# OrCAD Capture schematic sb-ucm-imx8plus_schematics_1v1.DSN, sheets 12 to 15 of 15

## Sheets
12 12. M.2 Key B, PCIe, USB3: size A3; title: SB-UCM-iMX8PLUS    12. PCIe
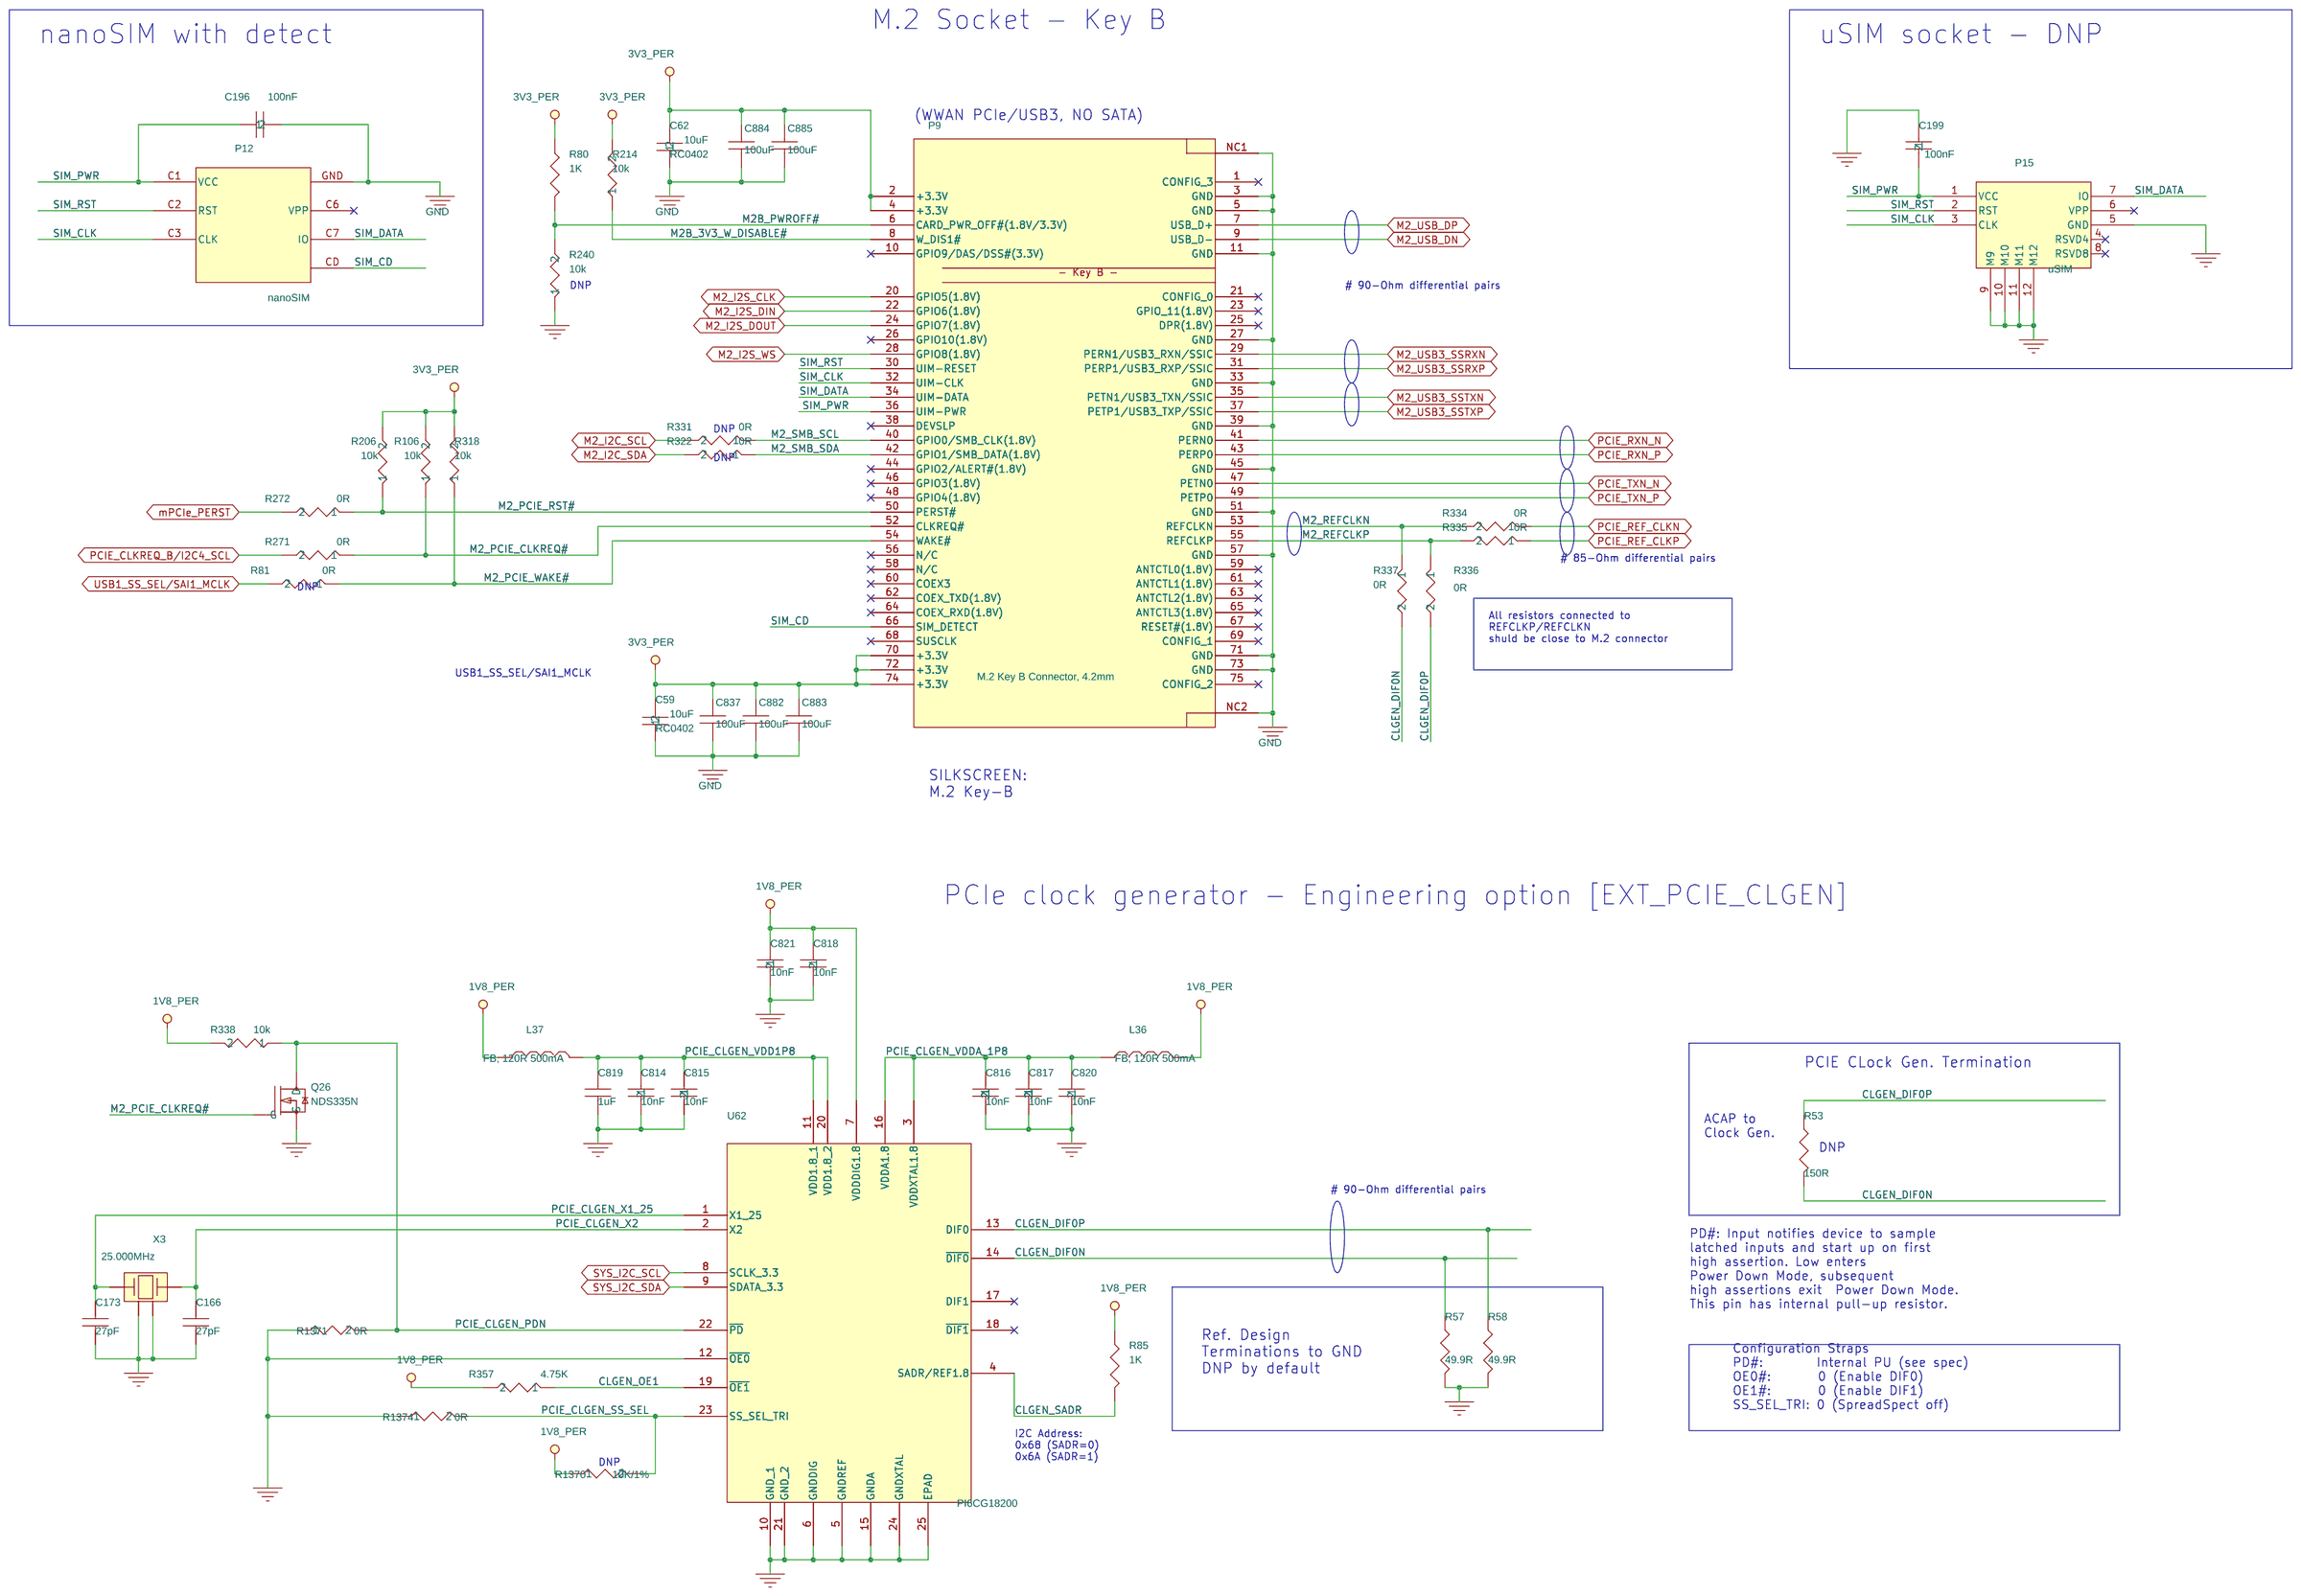
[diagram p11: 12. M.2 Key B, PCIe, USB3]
13 13. Power: size A3; title: SB-UCM-iMX8PLUS    13. POWER
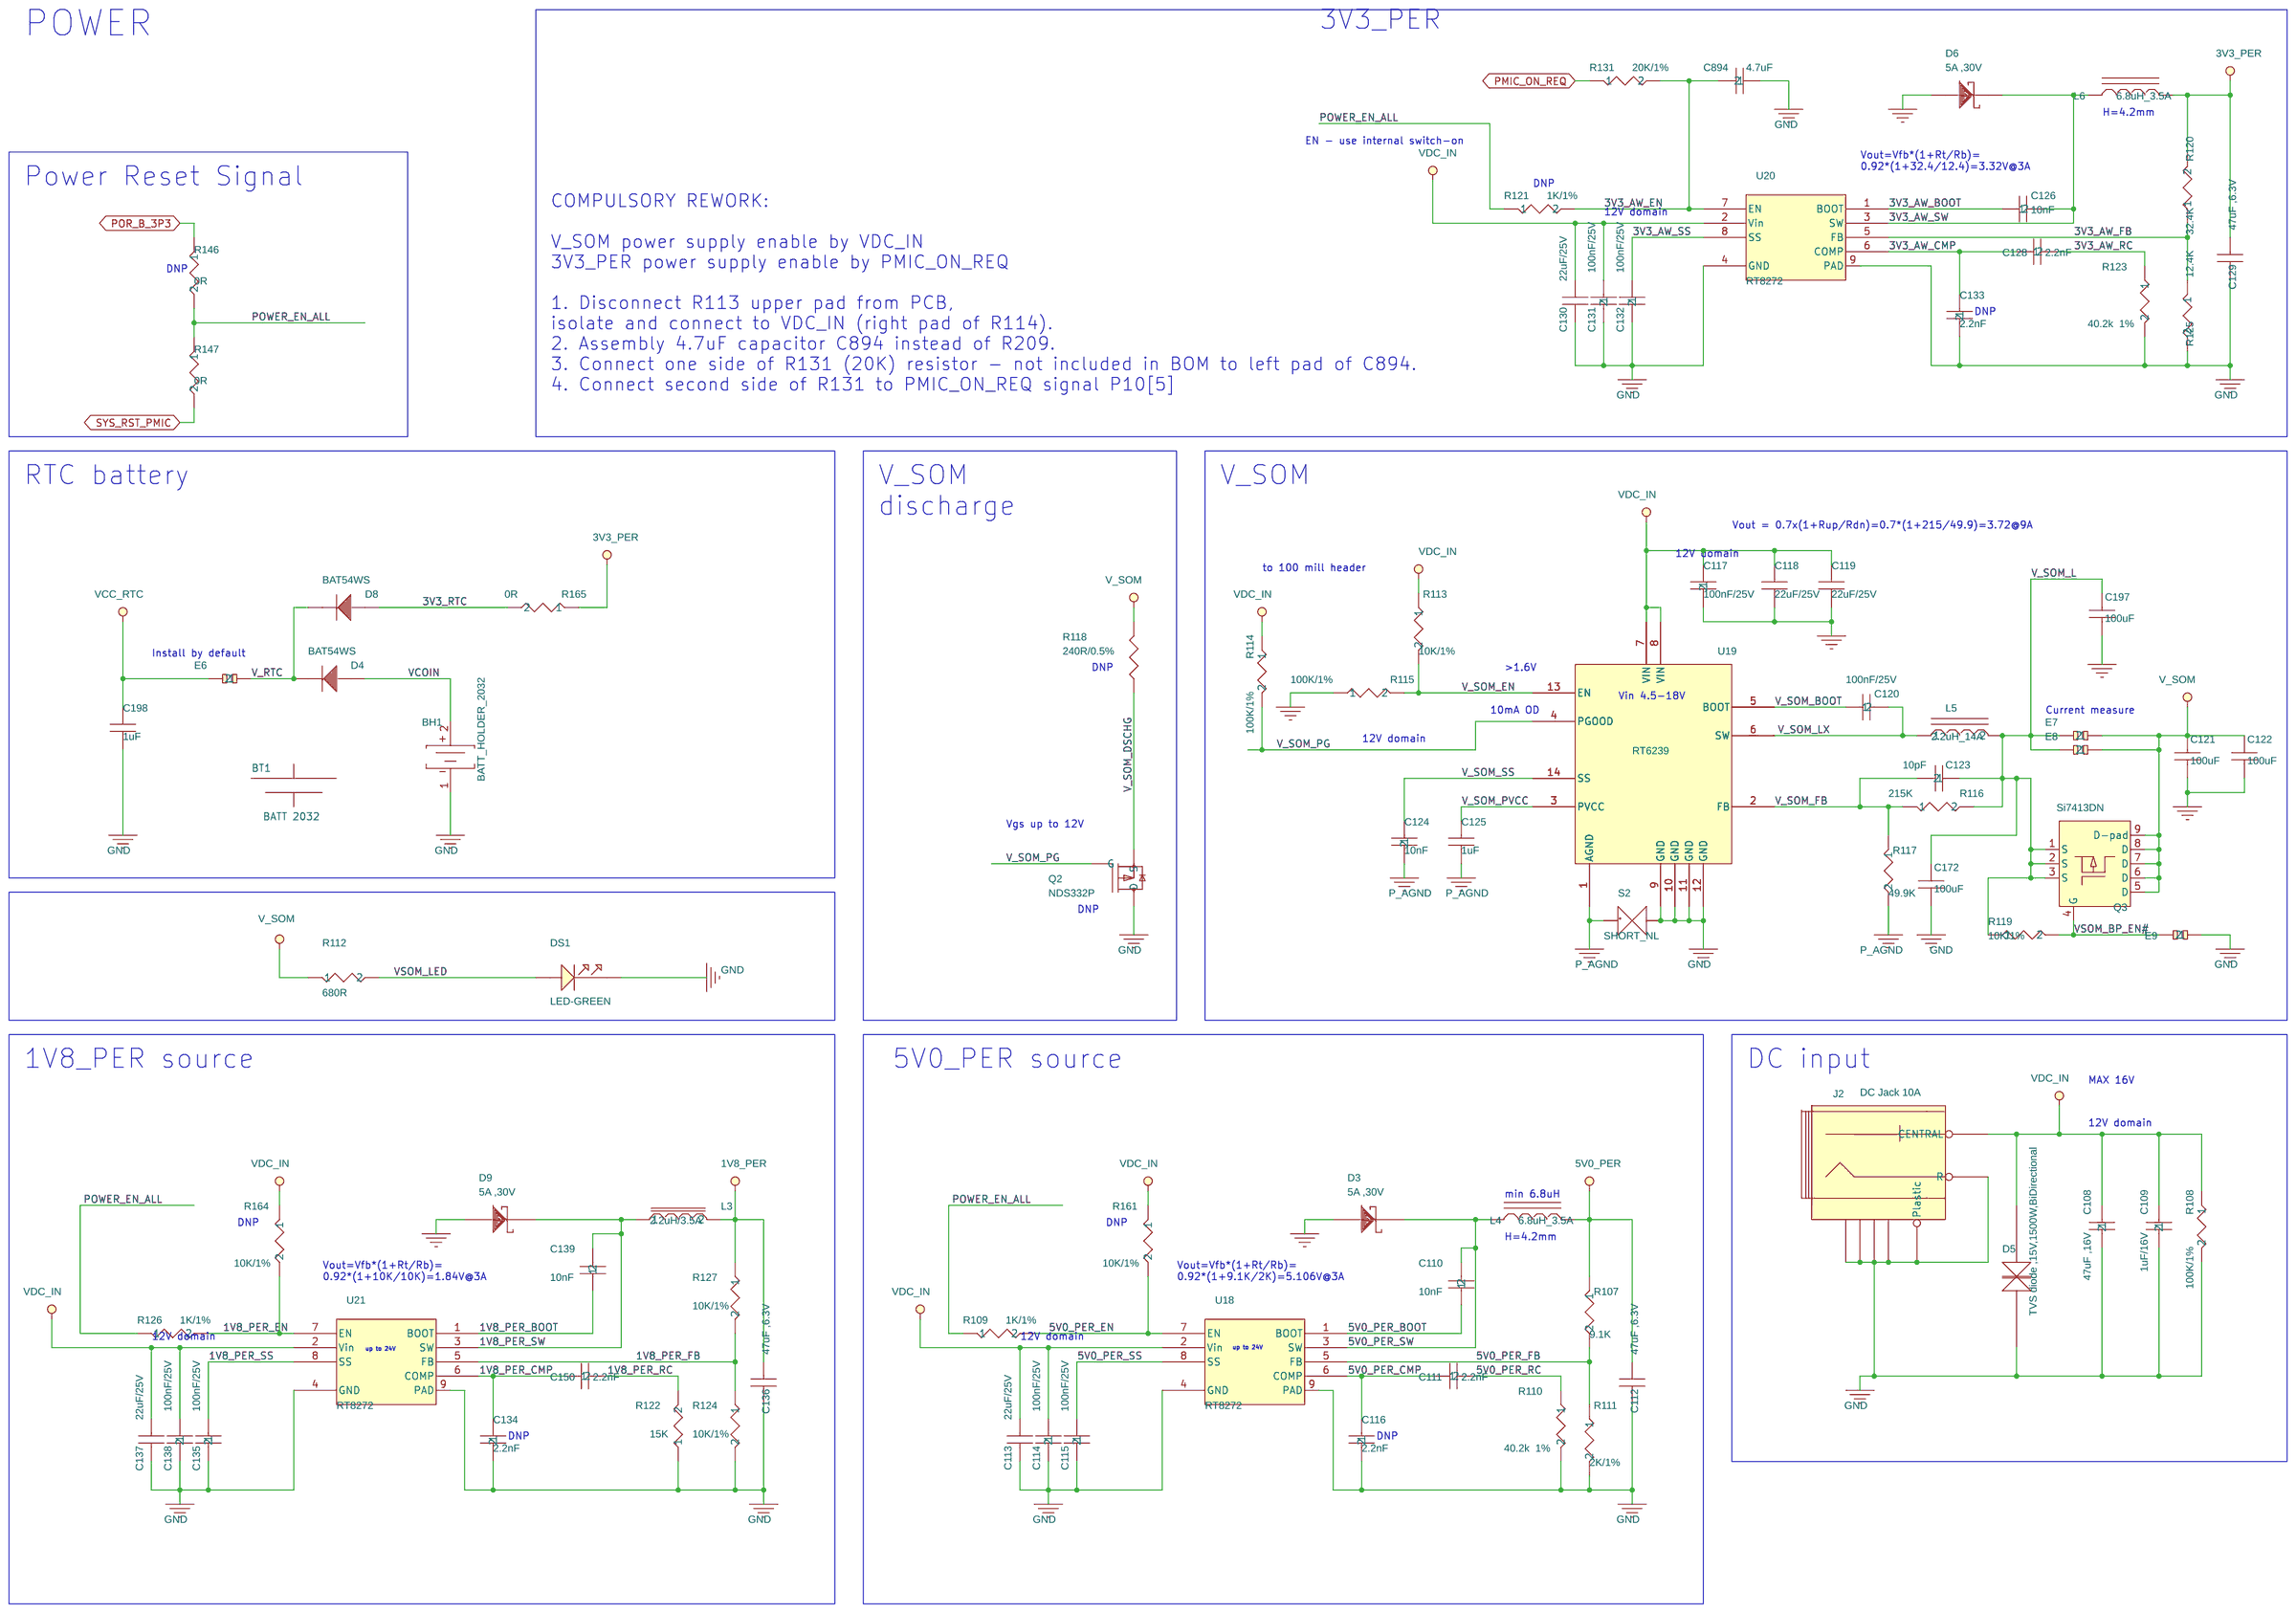
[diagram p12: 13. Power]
14 14. UART, RS232, SD, EEPROM: size A2; title: SB-UCM-iMX8PLUS      14. UART, RS232, SD Slot, EEPROM,GPIO
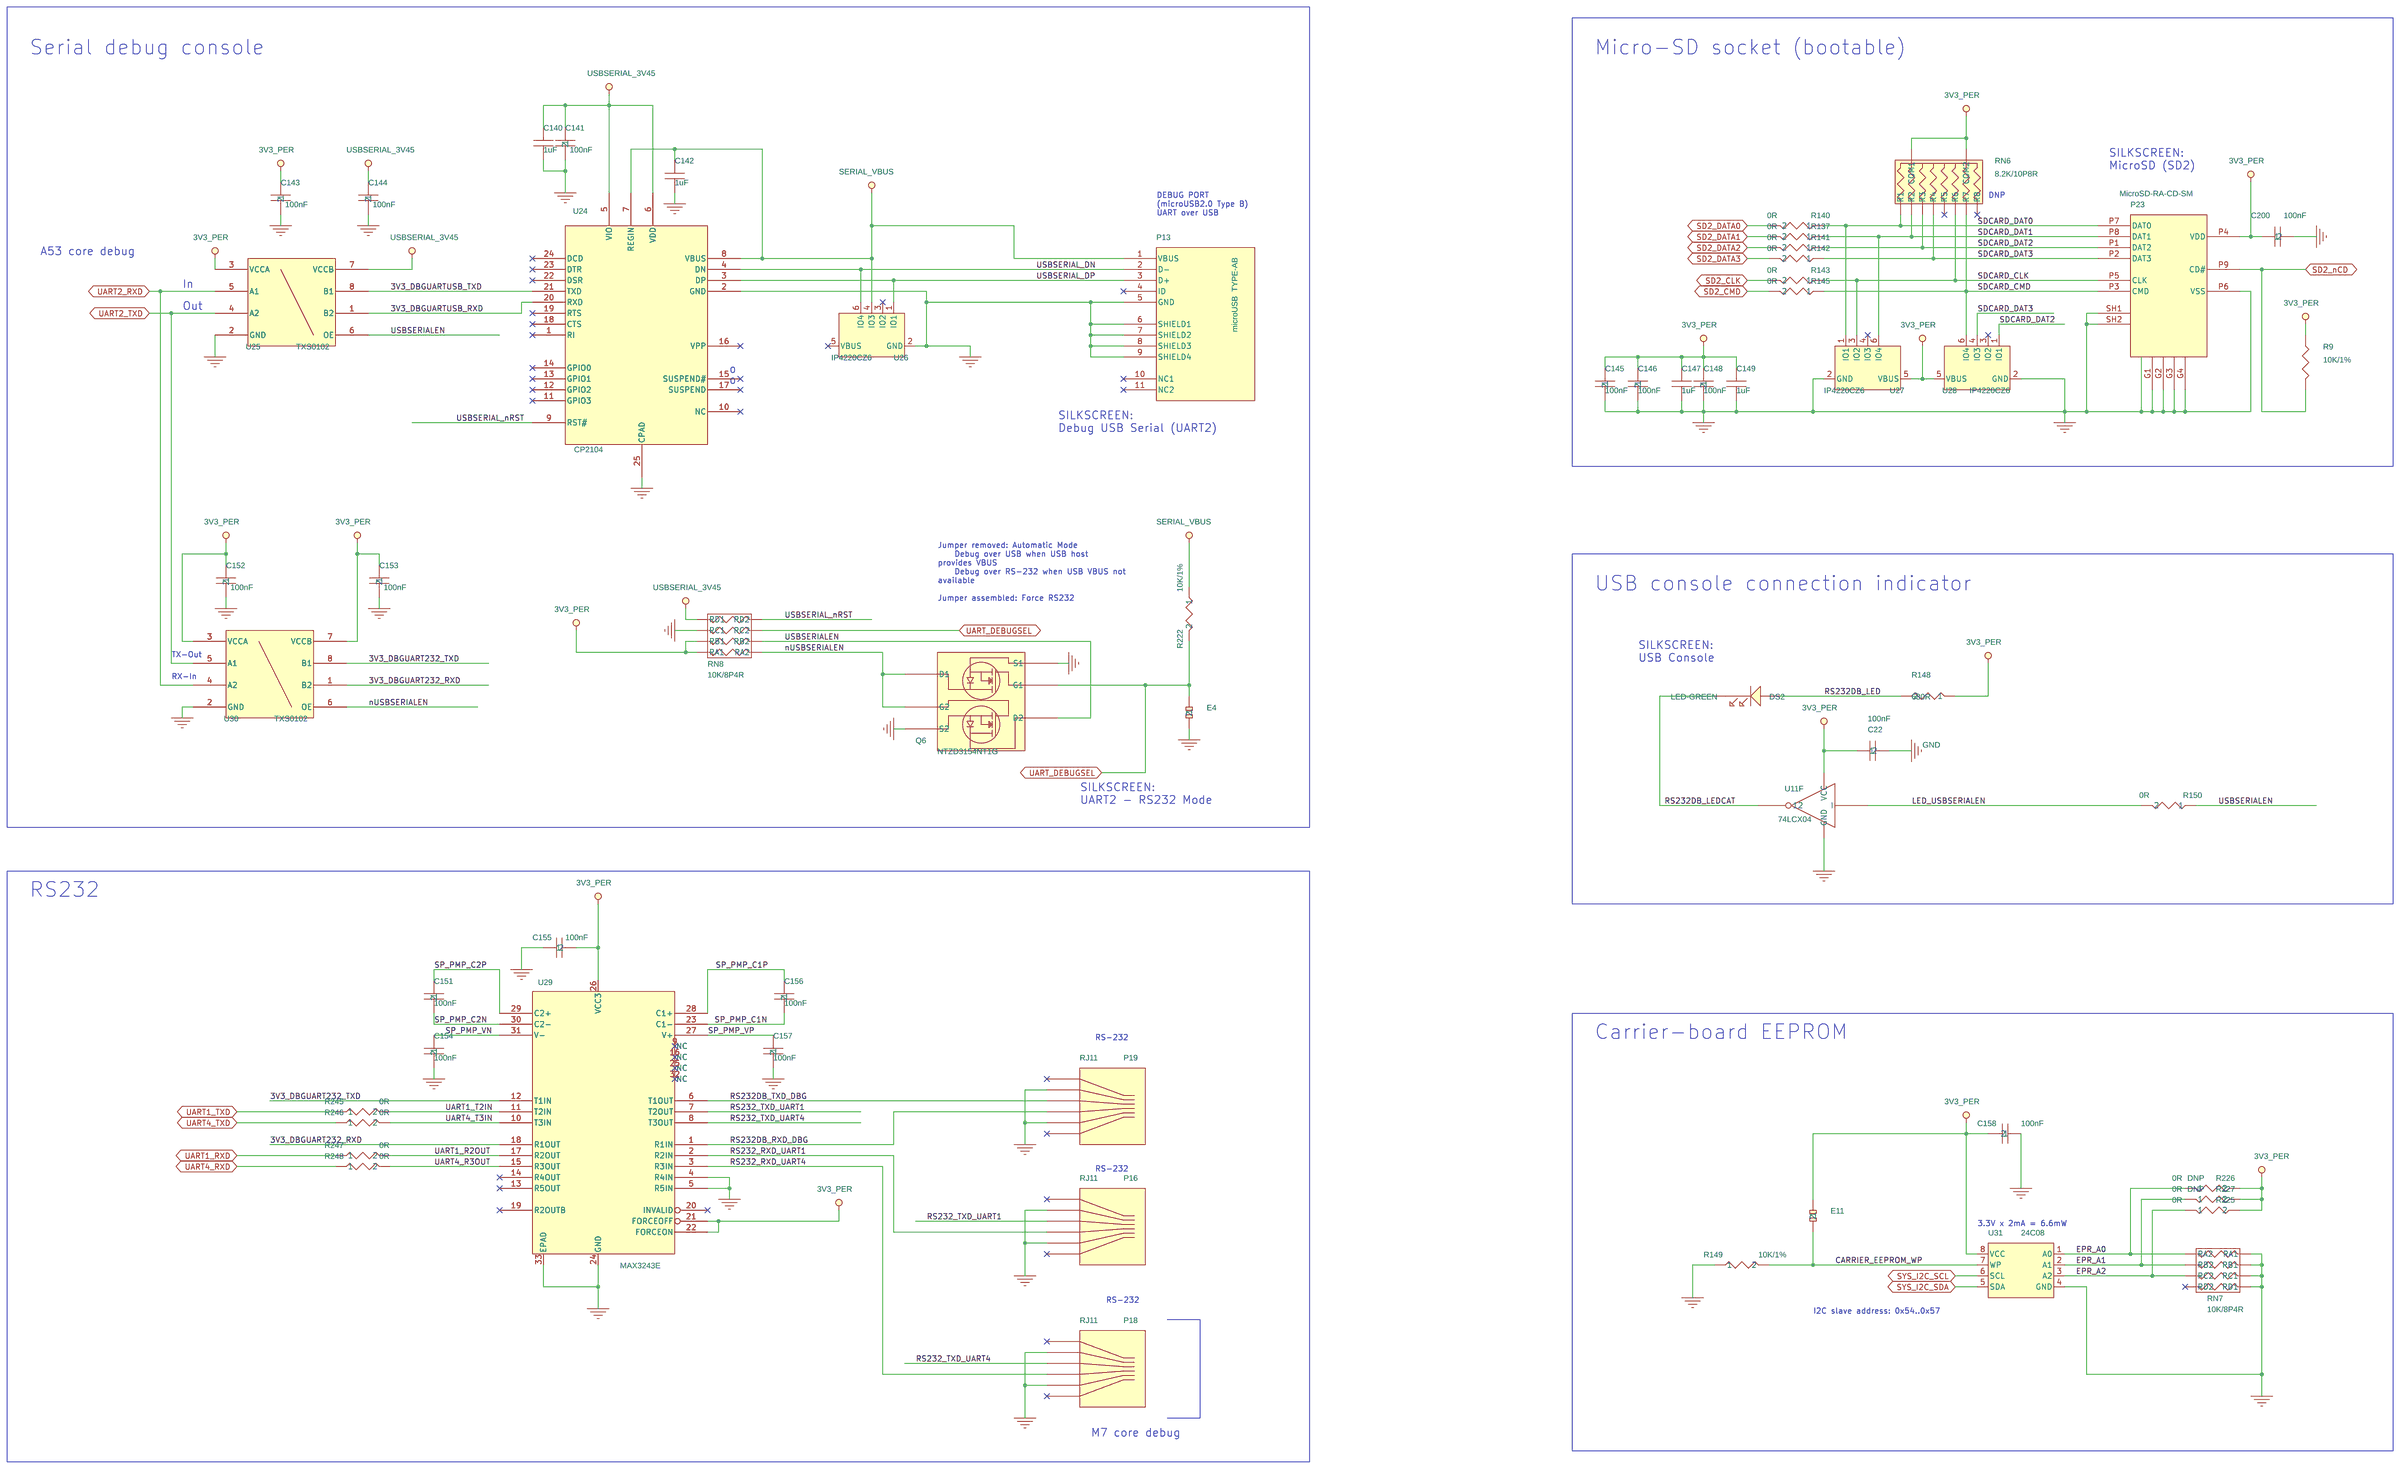
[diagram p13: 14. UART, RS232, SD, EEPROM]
15 15. Mechanical: size A3; title: SB-UCM-iMX8PLUS      15. Mechanical
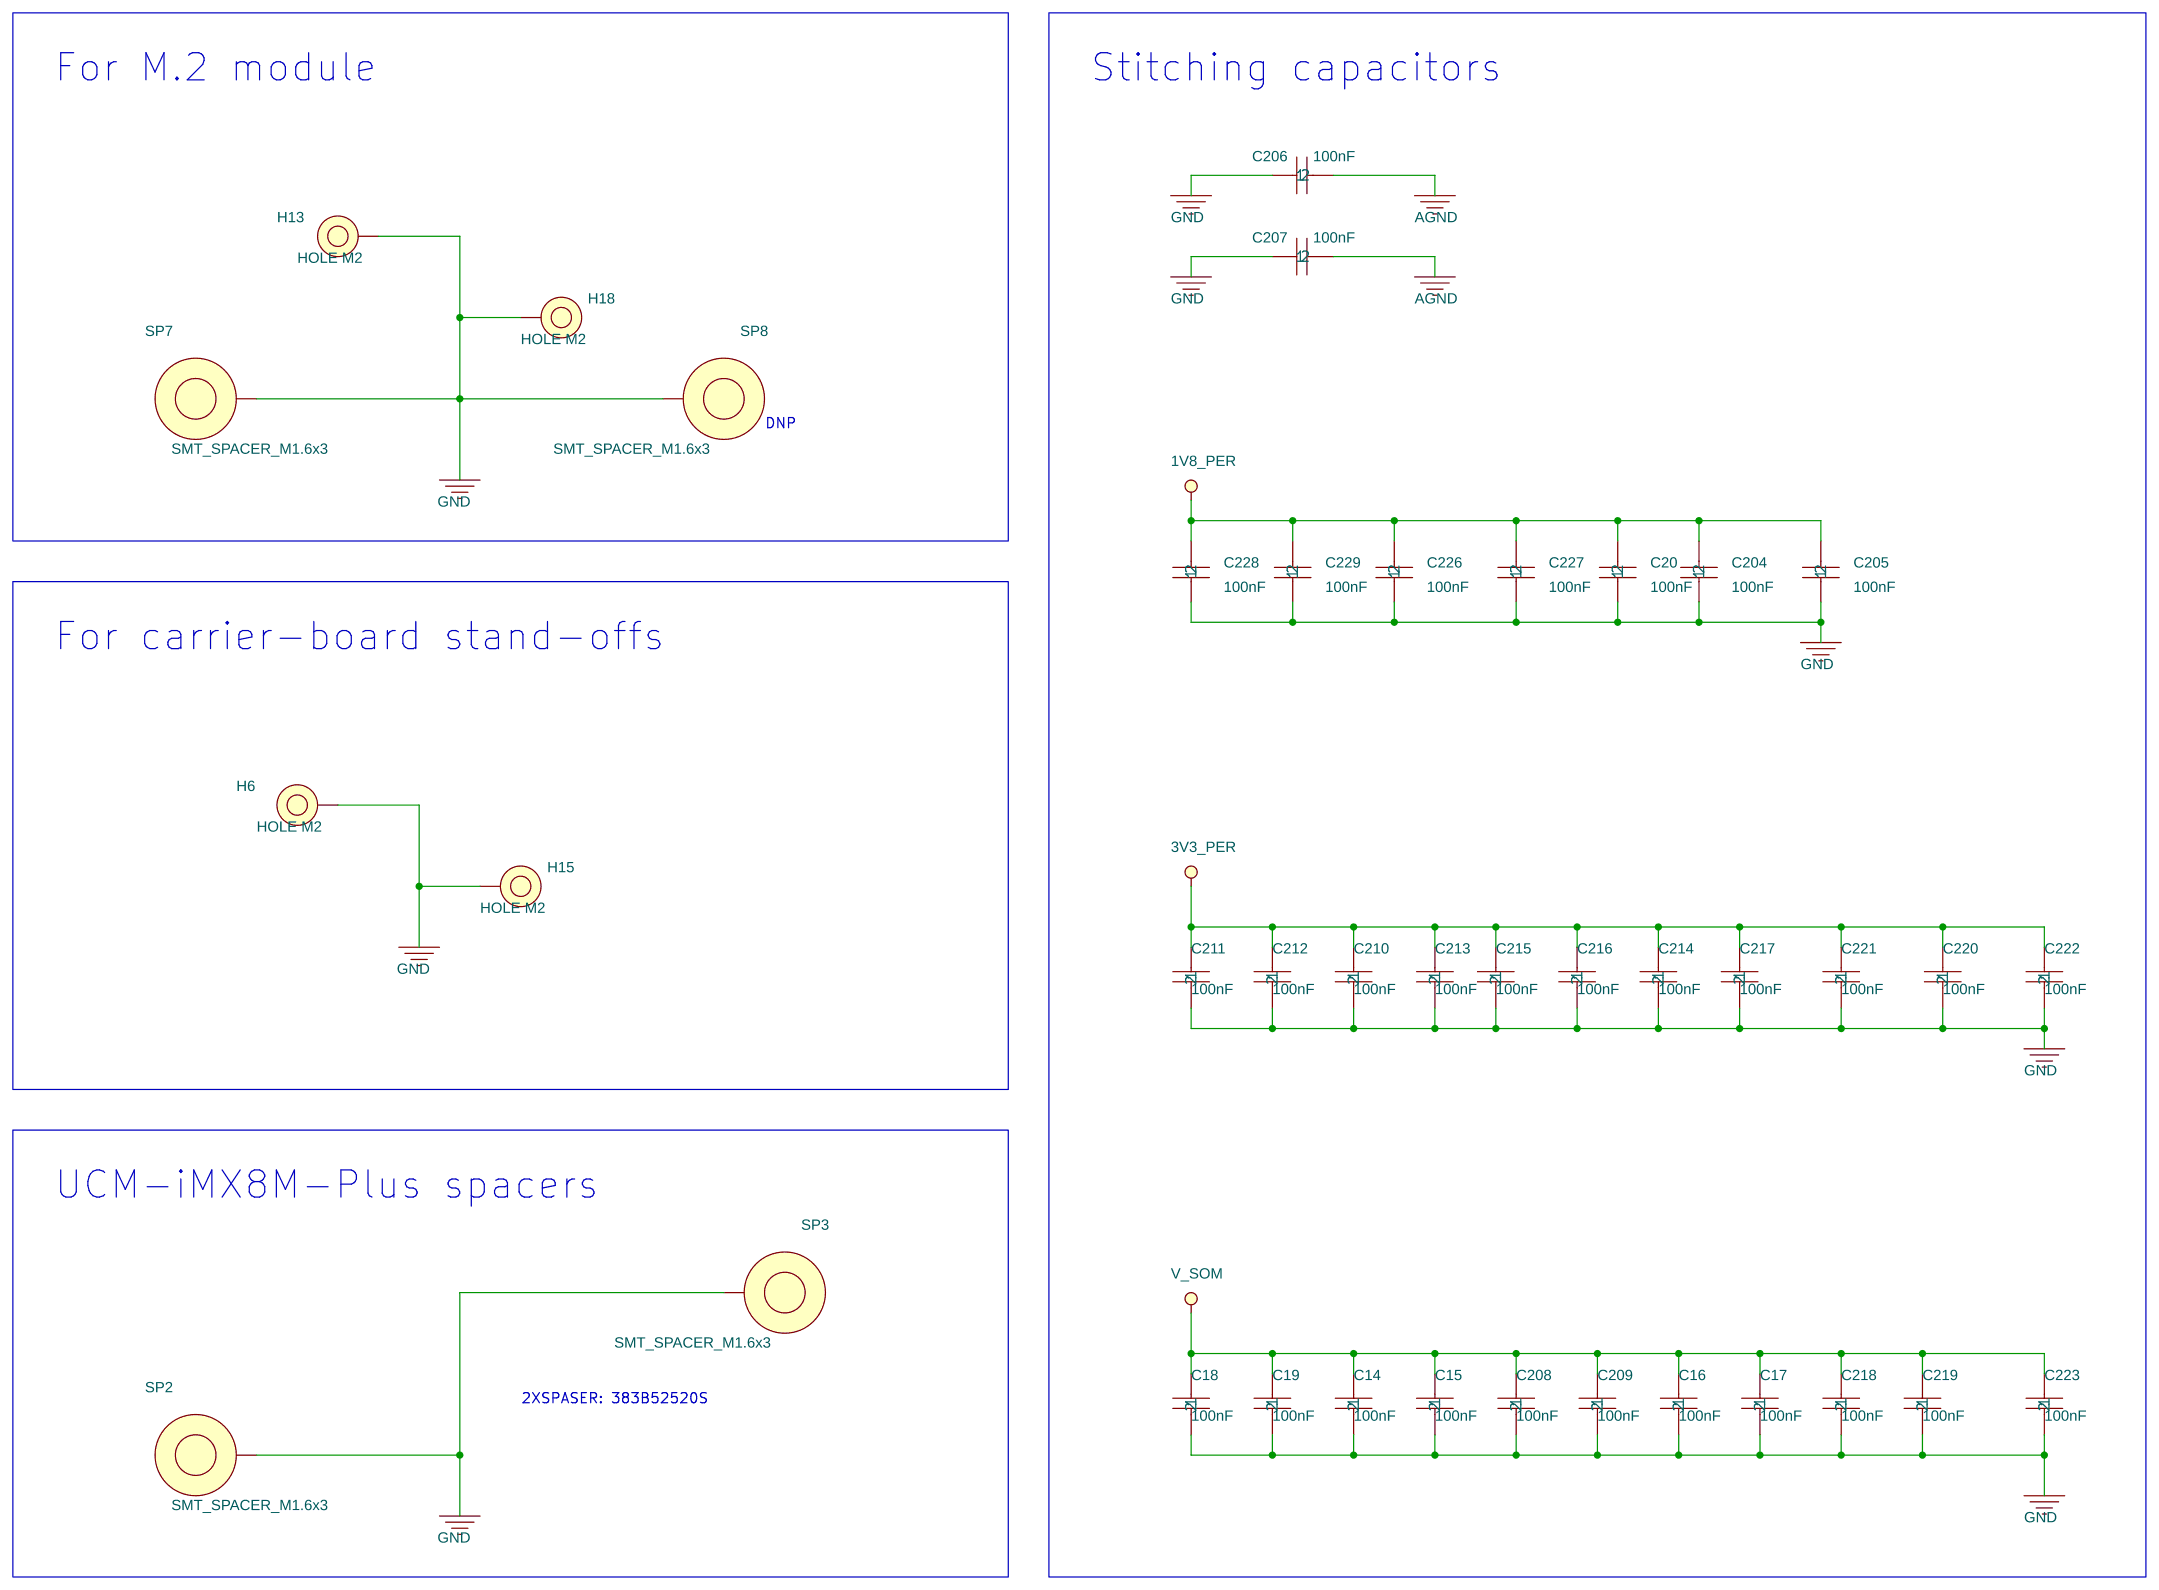
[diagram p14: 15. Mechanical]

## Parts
sheet 05. Audio Codec
U11  74LCX04  [TSSOP-14]  (sections A,B,F)
sheet 12. M.2 Key B, PCIe, USB3
C59  10uF  [RC0402]
C62  10uF  [RC0402]
C166  27pF  [RC0402]
C173  27pF  [RC0402]
C196  100nF  [RC0402]
C199  100nF  [RC0402]
C814  10nF  [RC0402]
C815  10nF  [RC0402]
C816  10nF  [RC0402]
C817  10nF  [RC0402]
C818  10nF  [RC0402]
C819  1uF  [RC0402]
C820  10nF  [RC0402]
C821  10nF  [RC0402]
C837  100uF  [C1206]
C882  100uF  [C1206]
C883  100uF  [C1206]
C884  100uF  [C1206]
C885  100uF  [C1206]
L36  FB, 120R 500mA  [FB0402]
L37  FB, 120R 500mA  [FB0402]
P9  M.2 Key B Connector, 4.2mm  [NGFF67P4HBkeySM]
P12  nanoSIM  [SKT-NanoSIM-CD-SM]
P15  uSIM  [SKT-MicroSIM6-SM]
Q26  NDS335N  [SOT23]
R53  150R  [RC0402]
R57  49.9R  [RC0402]
R58  49.9R  [RC0402]
R80  1K  [RC0402]
R81  0R  [RC0402]
R85  1K  [RC0402]
R106  10k  [RC0402]
R206  10k  [RC0402]
R214  10k  [RC0402]
R240  10k  [RC0402]
R271  0R  [RC0402]
R272  0R  [RC0402]
R318  10k  [RC0402]
R322  0R  [RC0402]
R331  0R  [RC0402]
R334  0R  [RC0402]
R335  0R  [RC0402]
R336  0R  [RC0402]
R337  0R  [RC0402]
R338  10k  [RC0402]
R357  4.75K  [RC0402]
R1370  10K/1%  [RC0402]
R1371  0R  [RC0402]
R1374  0R  [RC0402]
U62  PI6CG18200  [MO-220VGGD-8]
X3  25.000MHz  [OSC3225]
sheet 13. Power
BH1  BATT_HOLDER_2032  [BATTH20MM]
BT1  BATT 2032
C108  47uF ,16V  [C1210H2_5]
C109  1uF/16V  [RC0805]
C110  10nF  [RC0402]
C111  2.2nF  [RC0402]
C112  47uF ,6.3V  [C0805]
C113  22uF/25V  [C0805]
C114  100nF/25V  [RC0402]
C115  100nF/25V  [RC0402]
C116  2.2nF  [RC0402]
C117  100nF/25V  [RC0402]
C118  22uF/25V  [C0805]
C119  22uF/25V  [C0805]
C120  100nF/25V  [RC0402]
C121  100uF  [C1210H2_5]
C122  100uF  [C1210H2_5]
C123  10pF  [RC0402]
C124  10nF  [RC0402]
C125  1uF  [RC0402]
C126  10nF  [RC0402]
C128  2.2nF  [RC0402]
C129  47uF ,6.3V  [C0805]
C130  22uF/25V  [C0805]
C131  100nF/25V  [RC0402]
C132  100nF/25V  [RC0402]
C133  2.2nF  [RC0402]
C134  2.2nF  [RC0402]
C135  100nF/25V  [RC0402]
C136  47uF ,6.3V  [C0805]
C137  22uF/25V  [C0805]
C138  100nF/25V  [RC0402]
C139  10nF  [RC0402]
C150  2.2nF  [RC0402]
C172  100uF  [C1210H2_5]
C197  100uF  [C1210H2_5]
C198  1uF  [RC0402]
C894  4.7uF  [0402]
D3  5A ,30V  [SOD-128]
D4  BAT54WS  [SOD-323]
D5  TVS diode ,15V,1500W,BiDirectional  [DO-214AB]
D6  5A ,30V  [SOD-128]
D8  BAT54WS  [SOD-323]
D9  5A ,30V  [SOD-128]
DS1  LED-GREEN  [LED-1206]
E6  HDR1X2  [1X2THHDR]
E7  HDR1X2  [1X2THHDR]
E8  HDR1X2  [1X2THHDR]
E9  HDR1X2  [1X2THHDR]
J2  DC Jack 10A  [PJ-0810-TH]
L3  2.2uH/3.5A  [IND4_3x4_7SM]
L4  6.8uH_3.5A  [IND8_2x8_2]
L5  2.2uH_14A  [IND7x7_2SM]
L6  6.8uH_3.5A  [IND8_2x8_2]
Q2  NDS332P  [SOT23]
Q3  Si7413DN  [Powerpak1212-8]
R107  9.1K  [RC0402]
R108  100K/1%  [RC0402]
R109  1K/1%  [RC0402]
R110  40.2k  1%  [RC0402]
R111  2K/1%  [RC0402]
R112  680R  [RC0402]
R113  10K/1%  [RC0402]
R114  100K/1%  [RC0402]
R115  100K/1%  [RC0402]
R116  215K  [RC0402]
R117  49.9K  [RC0402]
R118  240R/0.5%  [RC0402]
R119  10K/1%  [RC0402]
R120  32.4K  [RC0402]
R121  1K/1%  [RC0402]
R122  15K  [RC0402]
R123  40.2k  1%  [RC0402]
R124  10K/1%  [RC0402]
R125  12.4K  [RC0402]
R126  1K/1%  [RC0402]
R127  10K/1%  [RC0402]
R131  20K/1%  [RC0402]
R146  0R  [RC0402]
R147  0R  [RC0402]
R161  10K/1%  [RC0402]
R164  10K/1%  [RC0402]
R165  0R  [RC0402]
S2  SHORT_NL  [SHORT_NL]
U18  RT8272  [PSOP-8-2X2]
U19  RT6239  [uQFN2x3-14]
U20  RT8272  [PSOP-8-2X2]
U21  RT8272  [PSOP-8-2X2]
sheet 14. UART, RS232, SD, EEPROM
C22  100nF  [RC0402]
C140  1uF  [RC0402]
C141  100nF  [RC0402]
C142  1uF  [RC0402]
C143  100nF  [RC0402]
C144  100nF  [RC0402]
C145  100nF  [RC0402]
C146  100nF  [RC0402]
C147  1uF  [RC0402]
C148  100nF  [RC0402]
C149  1uF  [RC0402]
C151  100nF  [RC0402]
C152  100nF  [RC0402]
C153  100nF  [RC0402]
C154  100nF  [RC0402]
C155  100nF  [RC0402]
C156  100nF  [RC0402]
C157  100nF  [RC0402]
C158  100nF  [RC0402]
C200  100nF  [RC0402]
DS2  LED-GREEN  [LED-1206]
E4  HDR1X2  [1X2THHDR]
E11  HDR1X2  [1X2THHDR]
P13  microUSB  TYPE-AB  [MICRO-USB-AB-RA-SM]
P16  RJ11  [RJ11TH6-6]
P18  RJ11  [RJ11TH6-6]
P19  RJ11  [RJ11TH6-6]
P23  MicroSD-RA-CD-SM  [MicroSD-RA-CD-SM]
Q6  NTZD3154NT1G  [SOT-563]
R9  10K/1%  [RC0402]
R137  0R  [RC0402]
R140  0R  [RC0402]
R141  0R  [RC0402]
R142  0R  [RC0402]
R143  0R  [RC0402]
R145  0R  [RC0402]
R148  680R  [RC0402]
R149  10K/1%  [RC0402]
R150  0R  [RC0402]
R222  10K/1%  [RC0402]
R225  0R  [RC0402]
R226  0R  [RC0402]
R227  0R  [RC0402]
R245  0R  [RC0402]
R246  0R  [RC0402]
R247  0R  [RC0402]
R248  0R  [RC0402]
RN6  8.2K/10P8R  [RESNET10P1206]
RN7  10K/8P4R  [RESNET8P0805]
RN8  10K/8P4R  [RESNET8P0805]
U24  CP2104  [MO-220VGGD-8]
U25  TXS0102  [MO-187DA-8]
U26  IP4220CZ6  [SOT23-6L]
U27  IP4220CZ6  [SOT23-6L]
U28  IP4220CZ6  [SOT23-6L]
U29  MAX3243E  [QFN5x5-32]
U30  TXS0102  [MO-187DA-8]
U31  24C08  [MO-229VCED-2]
sheet 15. Mechanical
C14  100nF  [RC0402]
C15  100nF  [RC0402]
C16  100nF  [RC0402]
C17  100nF  [RC0402]
C18  100nF  [RC0402]
C19  100nF  [RC0402]
C20  100nF  [RC0402]
C204  100nF  [RC0402]
C205  100nF  [RC0402]
C206  100nF  [RC0402]
C207  100nF  [RC0402]
C208  100nF  [RC0402]
C209  100nF  [RC0402]
C210  100nF  [RC0402]
C211  100nF  [RC0402]
C212  100nF  [RC0402]
C213  100nF  [RC0402]
C214  100nF  [RC0402]
C215  100nF  [RC0402]
C216  100nF  [RC0402]
C217  100nF  [RC0402]
C218  100nF  [RC0402]
C219  100nF  [RC0402]
C220  100nF  [RC0402]
C221  100nF  [RC0402]
C222  100nF  [RC0402]
C223  100nF  [RC0402]
C226  100nF  [RC0402]
C227  100nF  [RC0402]
C228  100nF  [RC0402]
C229  100nF  [RC0402]
H6  HOLE M2  [M2PAD]
H13  HOLE M2  [M2PAD]
H15  HOLE M2  [M2PAD]
H18  HOLE M2  [M2PAD]
SP2  SMT_SPACER_M1.6x3  [MINIPCIE-4-Spacer]
SP3  SMT_SPACER_M1.6x3  [MINIPCIE-4-Spacer]
SP7  SMT_SPACER_M1.6x3  [MINIPCIE-4-Spacer]
SP8  SMT_SPACER_M1.6x3  [MINIPCIE-4-Spacer]

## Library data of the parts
U11 = 74LCX04_sgl_gate_TSSOP-14: CLABCONF0: = SB-UCMIMX8PLUS
C59 = 100nF,_10V,_X7R,_10%,_0402: CLABCONF0: =SB-UCMIMX8PLUS; P/N: 151B10600S
C62 = 100nF,_10V,_X7R,_10%,_0402_3: CLABCONF0: =SB-UCMIMX8PLUS; P/N: 151B10600S
C166 C173 = 27pF,_50V,_X7R,_10%,_0402: CLABCONF0: =EXT_PCIE_CLGEN; P/N: 151D27000S
C158 C196 = 100nF,_10V,_X7R,_10%,_0402_2: CLABCONF0: =SB-UCMIMX8PLUS
C199 = 100nF,_10V,_X7R,_10%,_0402_1: CLABCONF0: DNP
C814 = 10nF,_25V,_X7R,_10%,_0402: CLABCONF0: =EXT_PCIE_CLGEN
C815 = 10nF,_25V,_X7R,_10%,_0402_1: CLABCONF0: =EXT_PCIE_CLGEN
C816 = 10nF,_25V,_X7R,_10%,_0402_2: CLABCONF0: =EXT_PCIE_CLGEN
C817 = 10nF,_25V,_X7R,_10%,_0402_3: CLABCONF0: =EXT_PCIE_CLGEN
C818 = 10nF,_25V,_X7R,_10%,_0402_4: CLABCONF0: =EXT_PCIE_CLGEN
C819 = 1uF,X5R,6.3V,0402: CLABCONF0: =EXT_PCIE_CLGEN
C820 = 10nF,_25V,_X7R,_10%,_0402_5: CLABCONF0: =EXT_PCIE_CLGEN
C821 = 10nF,_25V,_X7R,_10%,_0402_6: CLABCONF0: =EXT_PCIE_CLGEN
C121 C122 C172 C197 C837 C882-C885 = 100uF,_6.3V,_X5R,_20%,_1206: CLABCONF0: =SB-UCMIMX8PLUS
L36 L37 = Ferrit_330R-100Mhz,1.2A: CLABCONF0: =EXT_PCIE_CLGEN; P/N: 147D12102S
P9 = M_2.2_Key_B_Connector: CLABCONF0: =SB-UCMIMX8PLUS; P/N: 182K06702S
P12 = uSIM_SOCKET_2: CLABCONF0: =SB-UCMIMX8PLUS; P/N: 190I01100S
P15 = uSIM_SOCKET_0: CLABCONF0: DNP
Q26 = N-MOSFET,NDS335N,100mOhm@2.5V: CLABCONF0: =EXT_PCIE_CLGEN
R53 = 150R,1%,0402,1_16W_0: CLABCONF0: DNP; P/N: 161C15001S
R57 R58 = 150R,1%,0402,1_16W_0: CLABCONF0: DNP; P/N: 161C49R91S
R80 = RESISTOR: CLABCONF0: =SB-UCMIMX8PLUS; P/N: 161C10011S
R81 = 0R: CLABCONF0: DNP
R85 = RESISTOR: CLABCONF0: =EXT_PCIE_CLGEN; P/N: 161C10011S
R106 = 1M_,5%,_0402_5: CLABCONF0: =SB-UCMIMX8PLUS; P/N: 161C10021S
R206 = 1M_,5%,_0402_1: CLABCONF0: =SB-UCMIMX8PLUS; P/N: 161C10021S
R214 = 1M_,5%,_0402: CLABCONF0: =SB-UCMIMX8PLUS; P/N: 161C10021S
R240 = 1M_,5%,_0402_3: CLABCONF0: DNP; P/N: 161C10021S
R271 = 0R_1: CLABCONF0: =SB-UCMIMX8PLUS
R272 = 0R_3: CLABCONF0: =SB-UCMIMX8PLUS
R318 = 1M_,5%,_0402_4: CLABCONF0: =SB-UCMIMX8PLUS; P/N: 161C10021S
R322 = 0R_6: CLABCONF0: DNP
R331 = 0R_8: CLABCONF0: DNP
R334 = 0R_5: CLABCONF0: =SB-UCMIMX8PLUS AND NOT EXT_PCIE_CLGEN
R335 = 0R_7: CLABCONF0: =SB-UCMIMX8PLUS AND NOT EXT_PCIE_CLGEN
R336 = 0R_2: CLABCONF0: =EXT_PCIE_CLGEN
R337 = 0R_4: CLABCONF0: =EXT_PCIE_CLGEN
R338 = 1M_,5%,_0402_2: CLABCONF0: =EXT_PCIE_CLGEN; P/N: 161C10021S
R357 = 1M_,5%,_0402_6: CLABCONF0: =EXT_PCIE_CLGEN; P/N: 161C47511S
R1370 = 10K,1%,0402,1_16W: CLABCONF0: =EXT_PCIE_CLGEN
R1371 = 0R,_0402: CLABCONF0: =EXT_PCIE_CLGEN
R1374 = 0R,_0402_1: CLABCONF0: =EXT_PCIE_CLGEN
U62 = 9FGV0241AKLF_6: CLABCONF0: =EXT_PCIE_CLGEN; EN: 301-0-01673
X3 = XTAL,_25.000Mhz,_3x5mm: CLABCONF0: =EXT_PCIE_CLGEN; P/N: 141B25603I
BH1 = BATT_HOLDER_0: CLABCONF0: =SB-UCMIMX8PLUS
BT1 = BATT_2032: CLABCONF0: =SB-UCMIMX8PLUS
C108 = Cap.,_47uF,_16V,_X5R: CLABCONF0: =SB-UCMIMX8PLUS
C109 = 1uF,_16V,_X7R,_20%,_0805: CLABCONF0: =SB-UCMIMX8PLUS
C110 = 10nF,_25V,_X7R,_10%,_0402: CLABCONF0: =SB-UCMIMX8PLUS
C111 = 2.2nF,_50V,_X7R,_10%,_0402_5: CLABCONF0: =SB-UCMIMX8PLUS
C112 = 47uF,6.3V,X5R_1: CLABCONF0: =SB-UCMIMX8PLUS
C113 = Cap.,22uF,25V,_0805_1: CLABCONF0: =SB-UCMIMX8PLUS
C114 = 100nF_0402_25V_6: CLABCONF0: =SB-UCMIMX8PLUS
C115 = 100nF_0402_25V_3: CLABCONF0: =SB-UCMIMX8PLUS
C116 = 2.2nF,_50V,_X7R,_10%,_0402_2: CLABCONF0: DNP
C117 = 100nF_0402_25V_2: CLABCONF0: =SB-UCMIMX8PLUS
C118 = 22uF,25V,_0805: CLABCONF0: =SB-UCMIMX8PLUS
C119 = 22uF,25V,_0805_1: CLABCONF0: =SB-UCMIMX8PLUS
C120 = 100nF_0402_25V_5: CLABCONF0: =SB-UCMIMX8PLUS
C123 = 10pF,50V,NPO,_5%,_0402: CLABCONF0: =SB-UCMIMX8PLUS
C124 = 10nF,_25V,_X7R,_10%,_0402_3: CLABCONF0: =SB-UCMIMX8PLUS
C125 = 1uF,16V,0402: CLABCONF0: =SB-UCMIMX8PLUS
C126 = 10nF,_25V,_X7R,_10%,_0402_2: CLABCONF0: =SB-UCMIMX8PLUS
C128 = 2.2nF,_50V,_X7R,_10%,_0402_1: CLABCONF0: =SB-UCMIMX8PLUS
C129 = 47uF,6.3V,X5R_2: CLABCONF0: =SB-UCMIMX8PLUS
C130 = Cap.,22uF,25V,_0805: CLABCONF0: =SB-UCMIMX8PLUS
C131 = 100nF_0402_25V_7: CLABCONF0: =SB-UCMIMX8PLUS
C132 = 100nF_0402_25V_1: CLABCONF0: =SB-UCMIMX8PLUS
C133 = 2.2nF,_50V,_X7R,_10%,_0402: CLABCONF0: =SB-UCMIMX8PLUS
C134 = 2.2nF,_50V,_X7R,_10%,_0402_3: CLABCONF0: DNP
C135 = 100nF_0402_25V: CLABCONF0: =SB-UCMIMX8PLUS
C136 = 47uF,6.3V,X5R: CLABCONF0: =SB-UCMIMX8PLUS
C137 = Cap.,22uF,25V,_0805_2: CLABCONF0: =SB-UCMIMX8PLUS
C138 = 100nF_0402_25V_4: CLABCONF0: =SB-UCMIMX8PLUS
C139 = 10nF,_25V,_X7R,_10%,_0402_1: CLABCONF0: =SB-UCMIMX8PLUS
C150 = 2.2nF,_50V,_X7R,_10%,_0402_4: CLABCONF0: =SB-UCMIMX8PLUS
C140 C142 C147 C149 C198 = 1uF,X5R,6.3V,0402: CLABCONF0: =SB-UCMIMX8PLUS
C894 = 4.7uF_0402_10V_20%
D3 D6 D9 = Diode_Shotky,5A,30V: CLABCONF0: =SB-UCMIMX8PLUS
D4 D8 = BAT54WS_0: CLABCONF0: =SB-UCMIMX8PLUS
D5 = Diode_,TVS_,15V,1500W_0: CLABCONF0: =SB-UCMIMX8PLUS; P/N: 132D00150S
DS1 DS2 = LED-GREEN_1206_3: CLABCONF0: =SB-UCMIMX8PLUS
E4 E6 = HDR_1x2_100MIL_TH_JUMPER: CLABCONF0: =SB-UCMIMX8PLUS
E7 = HDR_1x2_100MIL_TH_JUMPER_2: CLABCONF0: =SB-UCMIMX8PLUS
E8 E11 = HDR_1x2_100MIL_TH_JUMPER_1: CLABCONF0: =SB-UCMIMX8PLUS
E9 = HDR_1x2_100MIL_TH_JUMPER_3: CLABCONF0: =SB-UCMIMX8PLUS
J2 = DC_Jack_,5.5_2_0.5,10A,20V: CLABCONF0: =SB-UCMIMX8PLUS
L3 = Ind,_2.2uH,_3A_5A,_58_mOhm: CLABCONF0: =SB-UCMIMX8PLUS; P/N: 147A2R206S
L4 L6 = IND_6.8uH_3.5A: CLABCONF0: =SB-UCMIMX8PLUS; P/N: 147A6R801S
L5 = IND_DELTA_MPL73-2R2_2.2uH_14A: CLABCONF0: =SB-UCMIMX8PLUS
Q2 = P-MOSFET,3A,20V,110mOhm@-1.8V: CLABCONF0: DNP
Q3 = Si7413DN: CLABCONF0: =SB-UCMIMX8PLUS
R107 = 100K,_0402: CLABCONF0: =SB-UCMIMX8PLUS; P/N: 161C91011S
R108 = 100K,_1%,_0402,_1_16W_2: CLABCONF0: =SB-UCMIMX8PLUS
R109 = 1K,1%,0402,1_16W_1: CLABCONF0: =SB-UCMIMX8PLUS
R110 = 40.2k_,1%: CLABCONF0: =SB-UCMIMX8PLUS
R111 = 10K,1%,0402,1_16W_5: CLABCONF0: =SB-UCMIMX8PLUS; P/N: 161C20011S
R112 R148 = 47K,_0402: CLABCONF0: =SB-UCMIMX8PLUS; P/N: 161C68001S
R113 = 10K,1%,0402,1_16W_3: CLABCONF0: =SB-UCMIMX8PLUS
R114 = 100K,_1%,_0402,_1_16W_1: CLABCONF0: =SB-UCMIMX8PLUS
R115 = 100K,_1%,_0402,_1_16W: CLABCONF0: =SB-UCMIMX8PLUS
R116 = 100K,_0402_1: CLABCONF0: =SB-UCMIMX8PLUS; P/N: 161C21531S
R117 = 100K,_0402_2: CLABCONF0: =SB-UCMIMX8PLUS; P/N: 161C49921S
R118 = 240R_resistor,_%0.5: CLABCONF0: DNP; P/N: 161C24003S
R119 R149 = 10K,1%,0402,1_16W: CLABCONF0: =SB-UCMIMX8PLUS
R120 = 32.4K,_0402: CLABCONF0: =SB-UCMIMX8PLUS; P/N: 161C32421S
R121 = 1K,1%,0402,1_16W_3: CLABCONF0: DNP
R122 = 0R: CLABCONF0: =SB-UCMIMX8PLUS; P/N: 161C15021S
R123 = 40.2k_,1%_1: CLABCONF0: =SB-UCMIMX8PLUS
R124 = 10K,1%,0402,1_16W_2: CLABCONF0: =SB-UCMIMX8PLUS
R125 = 4.99K,1%,0402,1_16W: CLABCONF0: =SB-UCMIMX8PLUS; P/N: 161C12421S
R126 = 1K,1%,0402,1_16W: CLABCONF0: =SB-UCMIMX8PLUS
R127 = 10K,1%,0402,1_16W_4: CLABCONF0: =SB-UCMIMX8PLUS
R131 = 1K,1%,0402,1_16W_2: CLABCONF0: DNP; P/N: 161C20021S
R146 = 0R,_0402_1_1: CLABCONF0: DNP
R147 R225 R246 = 0R,_0402_1: CLABCONF0: =SB-UCMIMX8PLUS
R161 = 10K,1%,0402,1_16W_1: CLABCONF0: DNP
R164 = 10K,1%,0402,1_16W_6: CLABCONF0: DNP
R165 = 0R,_0402_0: CLABCONF0: =SB-UCMIMX8PLUS; P/N: 161C00005S
S2 = MISC_SHORT_NL: CLABCONF0: DNP
U18 U20 U21 = RT8272,Converter,3A,24V: CLABCONF0: =SB-UCMIMX8PLUS
U19 = RT6239A_B: CLABCONF0: =SB-UCMIMX8PLUS; P/N: 123V08000S
C22 = 100nF,_10V,_X7R,_10%,_0402_5: CLABCONF0: =SB-UCMIMX8PLUS
C141 = 100nF,_10V,_X7R,_10%,_0402_9: CLABCONF0: =SB-UCMIMX8PLUS
C143 = 100nF,_10V,_X7R,_10%,_0402_6: CLABCONF0: =SB-UCMIMX8PLUS
C144 = 100nF,_10V,_X7R,_10%,_0402_13: CLABCONF0: =SB-UCMIMX8PLUS
C145 = 100nF,_10V,_X7R,_10%,_0402_3: CLABCONF0: =SB-UCMIMX8PLUS
C146 = 100nF,_10V,_X7R,_10%,_0402_10: CLABCONF0: =SB-UCMIMX8PLUS
C148 = 100nF,_10V,_X7R,_10%,_0402_8: CLABCONF0: =SB-UCMIMX8PLUS
C151 = 100nF,_10V,_X7R,_10%,_0402: CLABCONF0: =SB-UCMIMX8PLUS
C152 = 100nF,_10V,_X7R,_10%,_0402_12: CLABCONF0: =SB-UCMIMX8PLUS
C153 = 100nF,_10V,_X7R,_10%,_0402_11: CLABCONF0: =SB-UCMIMX8PLUS
C154 = 100nF,_10V,_X7R,_10%,_0402_7: CLABCONF0: =SB-UCMIMX8PLUS
C155 = 100nF,_10V,_X7R,_10%,_0402_14: CLABCONF0: =SB-UCMIMX8PLUS
C156 = 100nF,_10V,_X7R,_10%,_0402_15: CLABCONF0: =SB-UCMIMX8PLUS
C157 = 100nF,_10V,_X7R,_10%,_0402_4: CLABCONF0: =SB-UCMIMX8PLUS
C200 = 100nF,_10V,_X7R,_10%,_0402_1: CLABCONF0: =SB-UCMIMX8PLUS
P13 = Conn_1.,_Micro-USB,_B-Type: CLABCONF0: =SB-UCMIMX8PLUS; P/N: 180K00501S
P16 P18 P19 = RJ11: CLABCONF0: =SB-UCMIMX8PLUS
P23 = microSD_push-pull: CLABCONF0: =SB-UCMIMX8PLUS; P/N: 182K01300S
Q6 = MOSFET_N_DUAL_0_0.4A_20V: CLABCONF0: =SB-UCMIMX8PLUS
R9 = 10K,1%,0402,1_16W_0: CLABCONF0: =SB-UCMIMX8PLUS
R137 = 0R,_0402_1_9: CLABCONF0: =SB-UCMIMX8PLUS
R140 = 0R,_0402_1_8: CLABCONF0: =SB-UCMIMX8PLUS
R141 = 0R,_0402_1_3: CLABCONF0: =SB-UCMIMX8PLUS
R142 = 0R,_0402_1_6: CLABCONF0: =SB-UCMIMX8PLUS
R143 = 0R,_0402_1_5: CLABCONF0: =SB-UCMIMX8PLUS
R145 = 0R,_0402_1_7: CLABCONF0: =SB-UCMIMX8PLUS
R150 = 0R,_0402_1_1: CLABCONF0: =SB-UCMIMX8PLUS
R222 = 10K,1%,0402,1_16W_1: CLABCONF0: =SB-UCMIMX8PLUS
R226 = 0R,_0402_1_2: CLABCONF0: DNP
R227 = 0R,_0402_1_4: CLABCONF0: DNP
R245 = 0R,_0402: CLABCONF0: =SB-UCMIMX8PLUS
R247 = 0R,_0402_2: CLABCONF0: =SB-UCMIMX8PLUS
R248 = 0R,_0402_3: CLABCONF0: =SB-UCMIMX8PLUS
RN6 = RN,8.2K,10P8R@1206: CLABCONF0: DNP
RN7 RN8 = RN,10K,8P4R@0805: CLABCONF0: =SB-UCMIMX8PLUS
U24 = CP2104_1: CLABCONF0: =SB-UCMIMX8PLUS; P/N: 116A00140S
U25 U30 = TXS0102_0: CLABCONF0: =SB-UCMIMX8PLUS; P/N: 116A01020S
U26-U28 = IP4220CZ6_0: CLABCONF0: =SB-UCMIMX8PLUS
U29 = MAX3243E_RS-232_3T5R_BGA: CLABCONF0: =SB-UCMIMX8PLUS
U31 = 24C02,_serial_EE,_2KB,_I2C: CLABCONF0: =SB-UCMIMX8PLUS; P/N: 111S31000S
C14 = 100nF,_10V,_X7R,_10%,_0402_17: CLABCONF0: =SB-UCMIMX8PLUS; P/N: 151B10400S
C15 = 100nF,_10V,_X7R,_10%,_0402_27: CLABCONF0: =SB-UCMIMX8PLUS; P/N: 151B10400S
C16 = 100nF,_10V,_X7R,_10%,_0402_11: CLABCONF0: =SB-UCMIMX8PLUS; P/N: 151B10400S
C17 = 100nF,_10V,_X7R,_10%,_0402_21: CLABCONF0: =SB-UCMIMX8PLUS; P/N: 151B10400S
C18 = 100nF,_10V,_X7R,_10%,_0402_24: CLABCONF0: =SB-UCMIMX8PLUS; P/N: 151B10400S
C19 = 100nF,_10V,_X7R,_10%,_0402_26: CLABCONF0: =SB-UCMIMX8PLUS; P/N: 151B10400S
C20 = 100nF,_10V,_X7R,_10%,_0402_18: CLABCONF0: =SB-UCMIMX8PLUS; P/N: 151B10400S
C204 = 100nF,_10V,_X7R,_10%,_0402_2: CLABCONF0: =SB-UCMIMX8PLUS; P/N: 151B10400S
C205 = 100nF,_10V,_X7R,_10%,_0402_23: CLABCONF0: =SB-UCMIMX8PLUS; P/N: 151B10400S
C206 = 100nF,_10V,_X7R,_10%,_0402_25: CLABCONF0: =SB-UCMIMX8PLUS; P/N: 151B10400S
C207 = 100nF,_10V,_X7R,_10%,_0402_10: CLABCONF0: =SB-UCMIMX8PLUS; P/N: 151B10400S
C208 = 100nF,_10V,_X7R,_10%,_0402_14: CLABCONF0: =SB-UCMIMX8PLUS; P/N: 151B10400S
C209 = 100nF,_10V,_X7R,_10%,_0402_16: CLABCONF0: =SB-UCMIMX8PLUS; P/N: 151B10400S
C210 = 100nF,_10V,_X7R,_10%,_0402: CLABCONF0: =SB-UCMIMX8PLUS; P/N: 151B10400S
C211 = 100nF,_10V,_X7R,_10%,_0402_4: CLABCONF0: =SB-UCMIMX8PLUS; P/N: 151B10400S
C212 = 100nF,_10V,_X7R,_10%,_0402_6: CLABCONF0: =SB-UCMIMX8PLUS; P/N: 151B10400S
C213 = 100nF,_10V,_X7R,_10%,_0402_9: CLABCONF0: =SB-UCMIMX8PLUS; P/N: 151B10400S
C214 = 100nF,_10V,_X7R,_10%,_0402_13: CLABCONF0: =SB-UCMIMX8PLUS; P/N: 151B10400S
C215 = 100nF,_10V,_X7R,_10%,_0402_15: CLABCONF0: =SB-UCMIMX8PLUS; P/N: 151B10400S
C216 = 100nF,_10V,_X7R,_10%,_0402_20: CLABCONF0: =SB-UCMIMX8PLUS; P/N: 151B10400S
C217 = 100nF,_10V,_X7R,_10%,_0402_22: CLABCONF0: =SB-UCMIMX8PLUS; P/N: 151B10400S
C218 = 100nF,_10V,_X7R,_10%,_0402_30: CLABCONF0: =SB-UCMIMX8PLUS; P/N: 151B10400S
C219 = 100nF,_10V,_X7R,_10%,_0402_5: CLABCONF0: =SB-UCMIMX8PLUS; P/N: 151B10400S
C220 = 100nF,_10V,_X7R,_10%,_0402_3: CLABCONF0: =SB-UCMIMX8PLUS; P/N: 151B10400S
C221 = 100nF,_10V,_X7R,_10%,_0402_7: CLABCONF0: =SB-UCMIMX8PLUS; P/N: 151B10400S
C222 = 100nF,_10V,_X7R,_10%,_0402_28: CLABCONF0: =SB-UCMIMX8PLUS; P/N: 151B10400S
C223 = 100nF,_10V,_X7R,_10%,_0402_19: CLABCONF0: =SB-UCMIMX8PLUS; P/N: 151B10400S
C226 = 100nF,_10V,_X7R,_10%,_0402_29: CLABCONF0: =SB-UCMIMX8PLUS; P/N: 151B10400S
C227 = 100nF,_10V,_X7R,_10%,_0402_1: CLABCONF0: =SB-UCMIMX8PLUS; P/N: 151B10400S
C228 = 100nF,_10V,_X7R,_10%,_0402_8: CLABCONF0: =SB-UCMIMX8PLUS; P/N: 151B10400S
C229 = 100nF,_10V,_X7R,_10%,_0402_12: CLABCONF0: =SB-UCMIMX8PLUS; P/N: 151B10400S
H6 H13 H15 H18 = Hole,_Plated,_M2,_5mm._ext.: CLABCONF0: DNP
SP2 SP3 SP8 = SMT_SPACER_M2x3: CLABCONF0: DNP; P/N: 383B70030S
SP7 = SMT_SPACER_M2x3: CLABCONF0: =SB-UCMIMX8PLUS; P/N: 383B70030S

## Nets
1V8_PER: C20.2 C136.1 C204.2 C205.2 C226.2 C227.2 C228.2 C229.2 C818.1 C821.1 L3.2 L36.1 L37.2 R85.1 R127.1 R338.2 R357.2 R1370.1 U62.7(VDDDIG1.8) ; also on sheet 1 2 10
1V8_PER_BOOT: C139.1 U21.1(BOOT)
1V8_PER_CMP: C134.1 C150.1 U21.6(COMP)
1V8_PER_EN: R126.2 R164.2 U21.7(EN)
1V8_PER_FB: R124.1 R127.2 U21.5(FB)
1V8_PER_RC: C150.2 R122.2
1V8_PER_SS: C135.1 U21.8(SS)
1V8_PER_SW: C139.2 D9.CATHODE L3.1 U21.3(SW)
3V3_AW_BOOT: C126.1 U20.1(BOOT)
3V3_AW_CMP: C128.1 C133.1 U20.6(COMP)
3V3_AW_EN: C894.2 R121.2 R131.2 U20.7(EN)
3V3_AW_FB: R120.1 R125.1 U20.5(FB)
3V3_AW_RC: C128.2 R123.1
3V3_AW_SS: C132.1 U20.8(SS)
3V3_AW_SW: C126.2 D6.CATHODE L6.1 U20.3(SW)
3V3_DBGUART232_RXD: U29.18(R1OUT) U30.1(B2)
3V3_DBGUART232_TXD: U29.12(T1IN) U30.8(B1)
3V3_DBGUARTUSB_RXD: U24.20(RXD) U25.1(B2)
3V3_DBGUARTUSB_TXD: U24.21(TXD) U25.8(B1)
3V3_PER: C22.1 C59.2 C62.2 C129.1 C143.1 C145.1 C146.1 C147.1 C148.1 C149.1 C152.1 C153.1 C155.2 C158.2 C200.1 C210.1 C211.1 C212.1 C213.1 C214.1 C215.1 C216.1 C217.1 C220.1 C221.1 C222.1 C837.2 C882.2 C883.2 C884.2 C885.2 E11.1 L6.2 P9.2(+3.3V) P9.4(+3.3V) P9.70(+3.3V) P9.72(+3.3V) P9.74(+3.3V) P23.P4(VDD) R9.1 R80.1 R106.2 R120.2 R148.1 R165.1 R206.2 R214.2 R225.2 R226.2 R227.2 R318.2 RN6.5(COM1) RN6.10(COM2) RN8.1(RA1) RN8.2(RB1) U25.3(VCCA) U27.5(VBUS) U28.5(VBUS) U29.21(FORCEOFF) U29.22(FORCEON) U29.26(VCC3) U30.3(VCCA) U30.7(VCCB) U31.8(VCC) ; also on sheet 1 2 3 4 6 8 9 10 11
3V3_RTC: D8.ANODE R165.2
5V0_PER: C112.1 L4.2 R107.1 ; also on sheet 3 4 8 10
5V0_PER_BOOT: C110.1 U18.1(BOOT)
5V0_PER_CMP: C111.1 C116.1 U18.6(COMP)
5V0_PER_EN: R109.2 R161.2 U18.7(EN)
5V0_PER_FB: R107.2 R111.1 U18.5(FB)
5V0_PER_RC: C111.2 R110.1
5V0_PER_SS: C115.1 U18.8(SS)
5V0_PER_SW: C110.2 D3.CATHODE L4.1 U18.3(SW)
AGND: C206.2 C207.2 ; also on sheet 9
GND: BH1.1(MINUS) C14.2 C15.2 C16.2 C17.2 C18.2 C19.2 C20.1 C22.2 C59.1 C62.1 C108.2 C109.2 C112.2 C113.2 C114.2 C115.2 C116.2 C117.2 C118.2 C119.2 C121.1 C122.1 C129.2 C130.2 C131.2 C132.2 C133.2 C134.2 C135.2 C136.2 C137.2 C138.2 C140.2 C141.2 C142.2 C143.2 C144.2 C145.2 C146.2 C147.2 C148.2 C149.2 C152.2 C153.2 C154.2 C155.1 C157.2 C158.1 C166.2 C172.1 C173.2 C196.2 C197.1 C198.2 C199.1 C200.2 C204.1 C205.1 C206.1 C207.1 C208.2 C209.2 C210.2 C211.2 C212.2 C213.2 C214.2 C215.2 C216.2 C217.2 C218.2 C219.2 C220.2 C221.2 C222.2 C223.2 C226.1 C227.1 C228.1 C229.1 C814.2 C815.2 C816.2 C817.2 C818.2 C819.2 C820.2 C821.2 C837.1 C882.1 C883.1 C884.1 C885.1 C894.1 D3.ANODE D5.2 D6.ANODE D9.ANODE DS1.CATHODE E4.2 E9.1 H6.1 H13.1 H15.1 H18.1 J2.2(R) J2.3(Plastic) J2.SH1 J2.SH2 J2.SH3 J2.SH4 P9.3(GND) P9.5(GND) P9.11(GND) P9.27(GND) P9.33(GND) P9.39(GND) P9.45(GND) P9.51(GND) P9.57(GND) P9.71(GND) P9.73(GND) P9.NC1 P9.NC2 P12.GND P13.5(GND) P13.6(SHIELD1) P13.7(SHIELD2) P13.8(SHIELD3) P13.9(SHIELD4) P15.5(GND) P15.9(M9) P15.10(M10) P15.11(M11) P15.12(M12) P16.2 P16.5 P18.2 P18.5 P19.2 P19.5 P23.G1 P23.G2 P23.G3 P23.G4 P23.P6(VSS) P23.SH1 P23.SH2 Q2.3(D) Q6.1(S1) Q6.4(S2) Q26.2(S) R57.2 R58.2 R108.2 R110.2 R111.2 R115.1 R122.1 R123.2 R124.2 R125.2 R149.1 R240.1 R1371.1 R1374.1 RN7.1(RA1) RN7.2(RB1) RN7.3(RC1) RN7.4(RD1) RN8.3(RC1) S2.2 SP2.1 SP3.1 SP7.1 SP8.1 U18.4(GND) U18.9(PAD) U19.9(GND) U19.10(GND) U19.11(GND) U19.12(GND) U20.4(GND) U20.9(PAD) U21.4(GND) U21.9(PAD) U24.2(GND) U24.25(CPAD) U25.2(GND) U26.2(GND) U27.2(GND) U28.2(GND) U29.4(R4IN) U29.5(R5IN) U29.24(GND) U29.33(EPAD) U30.2(GND) U31.4(GND) U62.5(GNDREF) U62.6(GNDDIG) U62.10(GND_1) U62.12(~{OE0}) U62.15(GNDA) U62.21(GND_2) U62.24(GNDXTAL) U62.25(EPAD) X3.2 X3.4 ; also on sheet 1 2 3 4 6 7 8 9 10 11
VCC_RTC: C198.1 E6.2 ; also on sheet 6
CARRIER_EEPROM_WP: E11.2 R149.2 U31.7(WP)
CLGEN_DIF0N: R53.2 R57.1 R337.2 U62.14(~{DIF0})
CLGEN_DIF0P: R53.1 R58.1 R336.2 U62.13(DIF0)
CLGEN_OE1: R357.1 U62.19(~{OE1})
CLGEN_SADR: R85.2 U62.4(SADR/REF1.8)
EPR_A0: R226.1 RN7.8(RA2) U31.1(A0)
EPR_A1: R227.1 RN7.7(RB2) U31.2(A1)
EPR_A2: R225.1 RN7.6(RC2) U31.3(A2)
LED_USBSERIALEN: R150.2 U11.13(I)
M2_I2C_SCL: R331.2 ; also on sheet 10
M2_I2C_SDA: R322.2 ; also on sheet 10
M2_I2S_CLK: P9.20(GPIO5(1.8V)) ; also on sheet 10
M2_I2S_DIN: P9.22(GPIO6(1.8V)) ; also on sheet 10
M2_I2S_DOUT: P9.24(GPIO7(1.8V)) ; also on sheet 10
M2_I2S_WS: P9.28(GPIO8(1.8V)) ; also on sheet 10
M2_PCIE_CLKREQ#: P9.52(CLKREQ#) Q26.1(G) R106.1 R271.1
M2_PCIE_RST#: P9.50(PERST#) R206.1 R272.1
M2_PCIE_WAKE#: P9.54(WAKE#) R81.1 R318.1
M2_REFCLKN: P9.53(REFCLKN) R334.2 R337.1
M2_REFCLKP: P9.55(REFCLKP) R335.2 R336.1
M2_SMB_SCL: P9.40(GPIO0/SMB_CLK(1.8V)) R331.1
M2_SMB_SDA: P9.42(GPIO1/SMB_DATA(1.8V)) R322.1
M2_USB3_SSRXN: P9.29(PERN1/USB3_RXN/SSIC) ; also on sheet 8
M2_USB3_SSRXP: P9.31(PERP1/USB3_RXP/SSIC) ; also on sheet 8
M2_USB3_SSTXN: P9.35(PETN1/USB3_TXN/SSIC) ; also on sheet 8
M2_USB3_SSTXP: P9.37(PETP1/USB3_TXP/SSIC) ; also on sheet 8
M2_USB_DN: P9.9(USB_D-) ; also on sheet 8
M2_USB_DP: P9.7(USB_D+) ; also on sheet 8
M2B_3V3_W_DISABLE#: P9.8(W_DIS1#) R214.1
M2B_PWROFF#: P9.6(CARD_PWR_OFF#(1.8V/3.3V)) R80.2 R240.2
mPCIe_PERST: R272.2 ; also on sheet 10
nUSBSERIALEN: Q6.5(G2) Q6.6(D1) RN8.8(RA2) U30.6(OE)
P_AGND: C124.2 C125.2 R117.2 S2.1 U19.1(AGND)
PCIE_CLGEN_PDN: Q26.3(D) R338.1 R1371.2 U62.22(~{PD})
PCIE_CLGEN_SS_SEL: R1370.2 R1374.2 U62.23(SS_SEL_TRI)
PCIE_CLGEN_VDD1P8: C814.1 C815.1 C819.1 L37.1 U62.11(VDD1.8_1) U62.20(VDD1.8_2)
PCIE_CLGEN_VDDA_1P8: C816.1 C817.1 C820.1 L36.2 U62.3(VDDXTAL1.8) U62.16(VDDA1.8)
PCIE_CLGEN_X1_25: C173.1 U62.1(X1_25) X3.1
PCIE_CLGEN_X2: C166.1 U62.2(X2) X3.3
PCIE_CLKREQ_B/I2C4_SCL: R271.2 ; also on sheet 6 10
PCIE_REF_CLKN: R334.1 ; also on sheet 6
PCIE_REF_CLKP: R335.1 ; also on sheet 6
PCIE_RXN_N: P9.41(PERN0) ; also on sheet 6
PCIE_RXN_P: P9.43(PERP0) ; also on sheet 6
PCIE_TXN_N: P9.47(PETN0) ; also on sheet 6
PCIE_TXN_P: P9.49(PETP0) ; also on sheet 6
PMIC_ON_REQ: R131.1 ; also on sheet 6 10
POR_B_3P3: R146.1 ; also on sheet 6 10
POWER_EN_ALL: R109.1 R121.1 R126.1 R146.2 R147.1
RS232_RXD_UART1: P16.4 U29.2(R2IN)
RS232_RXD_UART4: P18.4 U29.3(R3IN)
RS232_TXD_UART1: P16.3 U29.7(T2OUT)
RS232_TXD_UART4: P18.3 U29.8(T3OUT)
RS232DB_LED: DS2.ANODE R148.2
RS232DB_LEDCAT: DS2.CATHODE U11.12
RS232DB_RXD_DBG: P19.4 U29.1(R1IN)
RS232DB_TXD_DBG: P19.3 U29.6(T1OUT)
SD2_CLK: R143.2 ; also on sheet 6
SD2_CMD: R145.2 ; also on sheet 6
SD2_DATA0: R140.2 ; also on sheet 6
SD2_DATA1: R137.2 ; also on sheet 6
SD2_DATA2: R141.2 ; also on sheet 6
SD2_DATA3: R142.2 ; also on sheet 6
SD2_nCD: P23.P9(CD#) R9.2 ; also on sheet 6
SDCARD_CLK: P23.P5(CLK) R143.1 RN6.7(R6) U27.3(IO2)
SDCARD_CMD: P23.P3(CMD) R145.1 RN6.8(R7) U28.6(IO4)
SDCARD_DAT0: P23.P7(DAT0) R140.1 RN6.1(R1) U27.1(IO1)
SDCARD_DAT1: P23.P8(DAT1) R137.1 RN6.2(R2) U27.6(IO4)
SDCARD_DAT2: P23.P1(DAT2) R141.1 RN6.3(R3) U28.1(IO1)
SDCARD_DAT3: P23.P2(DAT3) R142.1 RN6.4(R4) U28.4(IO3)
SERIAL_VBUS: C142.1 P13.1(VBUS) R222.1 U24.7(REGIN) U24.8(VBUS) U26.4(IO3)
SIM_CD: P9.66(SIM_DETECT) P12.CD
SIM_CLK: P9.32(UIM-CLK) P12.C3(CLK) P15.3(CLK)
SIM_DATA: P9.34(UIM-DATA) P12.C7(IO) P15.7(IO)
SIM_PWR: C196.1 C199.2 P9.36(UIM-PWR) P12.C1(VCC) P15.1(VCC)
SIM_RST: P9.30(UIM-RESET) P12.C2(RST) P15.2(RST)
SP_PMP_C1N: C156.2 U29.23(C1-)
SP_PMP_C1P: C156.1 U29.28(C1+)
SP_PMP_C2N: C151.2 U29.30(C2-)
SP_PMP_C2P: C151.1 U29.29(C2+)
SP_PMP_VN: C154.1 U29.31(V-)
SP_PMP_VP: C157.1 U29.27(V+)
SYS_I2C_SCL: U31.6(SCL) U62.8(SCLK_3.3) ; also on sheet 6 8 9 10
SYS_I2C_SDA: U31.5(SDA) U62.9(SDATA_3.3) ; also on sheet 6 8 9 10
SYS_RST_PMIC: R147.2 ; also on sheet 6 10
UART1_R2OUT: R247.2 U29.17(R2OUT)
UART1_RXD: R247.1 ; also on sheet 6 10
UART1_T2IN: R245.2 U29.11(T2IN)
UART1_TXD: R245.1 ; also on sheet 6 10
UART2_RXD: U25.5(A1) U30.4(A2) ; also on sheet 6 10
UART2_TXD: U25.4(A2) U30.5(A1) ; also on sheet 6 10
UART4_R3OUT: R248.2 U29.15(R3OUT)
UART4_RXD: R248.1 ; also on sheet 6 10
UART4_T3IN: R246.2 U29.10(T3IN)
UART4_TXD: R246.1 ; also on sheet 6 10
UART_DEBUGSEL: E4.1 Q6.2(G1) R222.2 RN8.6(RC2) ; also on sheet 10
USB1_SS_SEL/SAI1_MCLK: R81.2 ; also on sheet 6 10
USBSERIAL_3V45: C140.1 C141.1 C144.1 RN8.4(RD1) U24.5(VIO) U24.6(VDD) U25.7(VCCB)
USBSERIAL_DN: P13.2(D-) U24.4(DN) U26.6(IO4)
USBSERIAL_DP: P13.3(D+) U24.3(DP) U26.1(IO1)
USBSERIAL_nRST: RN8.5(RD2) U24.9(RST#)
USBSERIALEN: Q6.3(D2) R150.1 RN8.7(RB2) U25.6(OE)
V_RTC: D4.CATHODE D8.CATHODE E6.1
V_SOM: C14.1 C15.1 C16.1 C17.1 C18.1 C19.1 C121.2 C122.2 C208.1 C209.1 C218.1 C219.1 C223.1 E7.1 E8.1 Q3.5(D) Q3.6(D) Q3.7(D) Q3.8(D) Q3.9(D-pad) R112.1 R118.1 ; also on sheet 6
V_SOM_BOOT: C120.1 U19.5(BOOT)
V_SOM_DSCHG: Q2.2(S) R118.2
V_SOM_EN: R113.2 R115.2 U19.13(EN)
V_SOM_FB: C123.2 R116.1 R117.1 U19.2(FB)
V_SOM_L: C123.1 C172.2 C197.2 E7.2 E8.2 L5.2 Q3.1(S) Q3.2(S) Q3.3(S) R116.2 R119.1
V_SOM_LX: C120.2 L5.1 U19.6(SW)
V_SOM_PG: Q2.1(G) R114.2 U19.4(PGOOD)
V_SOM_PVCC: C125.1 U19.3(PVCC)
V_SOM_SS: C124.1 U19.14(SS)
VCOIN: BH1.2(PLUS) D4.ANODE
VDC_IN: C108.1 C109.1 C113.1 C114.1 C117.1 C118.1 C119.1 C130.1 C131.1 C137.1 C138.1 D5.1 J2.1(CENTRAL) R108.1 R113.1 R114.1 R161.1 R164.1 U18.2(Vin) U19.7(VIN) U19.8(VIN) U20.2(Vin) U21.2(Vin)
VSOM_BP_EN#: E9.2 Q3.4(G) R119.2
VSOM_LED: DS1.ANODE R112.2

Not connected (* = marked no-connect by the designer): P9 1(CONFIG_3)* 10(GPIO9/DAS/DSS#(3.3V))* 21(CONFIG_0)* 23(GPIO_11(1.8V))* 25(DPR(1.8V))* 26(GPIO10(1.8V))* 38(DEVSLP)* 44(GPIO2/ALERT#(1.8V))* 46(GPIO3(1.8V))* 48(GPIO4(1.8V))* 56(N/C)* 58(N/C)* 59(ANTCTL0(1.8V))* 60(COEX3)* 61(ANTCTL1(1.8V))* 62(COEX_TXD(1.8V))* 63(ANTCTL2(1.8V))* 64(COEX_RXD(1.8V))* 65(ANTCTL3(1.8V))* 67(RESET#(1.8V))* 68(SUSCLK)* 69(CONFIG_1)* 75(CONFIG_2)*; P12 C6(VPP)*; P13 4(ID)* 10(NC1)* 11(NC2)*; P15 4(RSVD4)* 6(VPP)* 8(RSVD8)*; P16 1* 6*; P18 1* 6*; P19 1* 6*; RN6 6(R5)* 9(R8)*; RN7 5(RD2)*; U24 1(RI)* 10(NC)* 11(GPIO3)* 12(GPIO2)* 13(GPIO1)* 14(GPIO0)* 15(SUSPEND#)* 16(VPP)* 17(SUSPEND)* 18(CTS)* 19(RTS)* 22(DSR)* 23(DTR)* 24(DCD)*; U26 3(IO2)* 5(VBUS)*; U27 4(IO3)*; U28 3(IO2)*; U29 9(NC)* 13(R5OUT)* 14(R4OUT)* 16(NC)* 19(R2OUTB)* 20(INVALID)* 25(NC)* 32(NC)*; U62 17(DIF1)* 18(~{DIF1})*

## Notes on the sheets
sheet 12
- M.2 Socket - Key B
- nanoSIM with detect
- uSIM socket - DNP
- (WWAN PCIe/USB3, NO SATA)
- DNP
- # 90-Ohm differential pairs
- DNP
- DNP
- # 85-Ohm differential pairs
- DNP
- All resistors connected to
  REFCLKP/REFCLKN
  shuld be close to M.2 connector
- USB1_SS_SEL/SAI1_MCLK
- SILKSCREEN:
  M.2 Key-B
- PCIe clock generator - Engineering option [EXT_PCIE_CLGEN]
- PCIE CLock Gen. Termination
- ACAP to
  Clock Gen.
- DNP
- # 90-Ohm differential pairs
- PD#: Input notifies device to sample
  latched inputs and start up on first
  high assertion. Low enters
  Power Down Mode, subsequent
  high assertions exit  Power Down Mode.
  This pin has internal pull-up resistor.
- Ref. Design
  Terminations to GND
  DNP by default
- Configuration Straps
  PD#:        Internal PU (see spec)
  OE0#:       0 (Enable DIF0)
  OE1#:       0 (Enable DIF1)
  SS_SEL_TRI: 0 (SpreadSpect off)
- I2C Address:
  0x68 (SADR=0)
  0x6A (SADR=1)
- DNP
sheet 13
- POWER
- 3V3_PER
- H=4.2mm
- EN - use internal switch-on
- Power Reset Signal
- Vout=Vfb*(1+Rt/Rb)=
  0.92*(1+32.4/12.4)=3.32V@3A
- DNP
- COMPULSORY REWORK:
  V_SOM power supply enable by VDC_IN
  3V3_PER power supply enable by PMIC_ON_REQ
  1. Disconnect R113 upper pad from PCB,
  isolate and connect to VDC_IN (right pad of R114).
  2. Assembly 4.7uF capacitor C894 instead of R209.
  3. Connect one side of R131 (20K) resistor - not included in BOM to left pad of C894.
  4. Connect second side of R131 to PMIC_ON_REQ signal P10[5]
- 12V domain
- DNP
- DNP
- RTC battery
- V_SOM
  discharge
- V_SOM
- Vout = 0.7x(1+Rup/Rdn)=0.7*(1+215/49.9)=3.72@9A
- 12V domain
- to 100 mill header
- Install by default
- DNP
- >1.6V
- Vin 4.5-18V
- 10mA OD
- Current measure
- 12V domain
- Vgs up to 12V
- DNP
- 1V8_PER source
- 5V0_PER source
- DC input
- MAX 16V
- 12V domain
- min 6.8uH
- DNP
- DNP
- H=4.2mm
- Vout=Vfb*(1+Rt/Rb)=
  0.92*(1+10K/10K)=1.84V@3A
- Vout=Vfb*(1+Rt/Rb)=
  0.92*(1+9.1K/2K)=5.106V@3A
- 12V domain
- 12V domain
- up to 24V
- up to 24V
- DNP
- DNP
sheet 14
- Serial debug console
- Micro-SD socket (bootable)
- SILKSCREEN:
  MicroSD (SD2)
- DEBUG PORT
  (microUSB2.0 Type B)
  UART over USB
- DNP
- A53 core debug
- In
- Out
- O
- O
- SILKSCREEN:
  Debug USB Serial (UART2)
- Jumper removed: Automatic Mode
      Debug over USB when USB host
  provides VBUS
      Debug over RS-232 when USB VBUS not
  available
  Jumper assembled: Force RS232
- USB console connection indicator
- SILKSCREEN:
  USB Console
- TX-Out
- RX-In
- SILKSCREEN:
  UART2 - RS232 Mode
- RS232
- Carrier-board EEPROM
- RS-232
- RS-232
- 3.3V x 2mA = 6.6mW
- RS-232
- I2C slave address: 0x54..0x57
- M7 core debug
sheet 15
- For M.2 module
- Stitching capacitors
- DNP
- For carrier-board stand-offs
- UCM-iMX8M-Plus spacers
- 2XSPASER: 383B52520S
